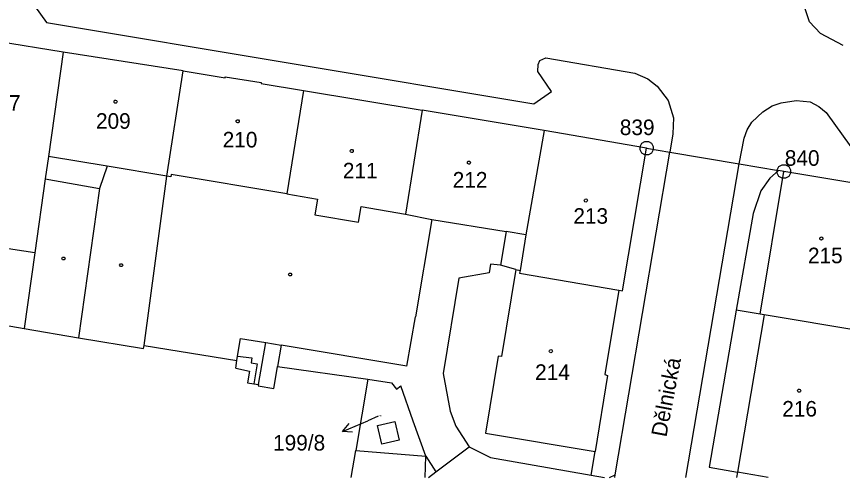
# Model space of a CAD drawing. Extents: x -851495 to -851222, y -1010479 to -1010202.
# Drawn here: x -851400.4 to -851310.2, y -1010478.7 to -1010428.3 of the extents above; entities that cross this region are included whole.
import ezdxf

# ---------------------------------------------------------------- set-up
doc = ezdxf.new("R2010")
doc.units = 0
for name, color, linetype in [('1', 7, 'Continuous'), ('12', 7, 'Continuous'), ('2', 7, 'Continuous'), ('4', 7, 'Continuous'), ('5', 7, 'Continuous'), ('7', 7, 'Continuous'), ('8', 7, 'Continuous')]:
    doc.layers.add(name, color=color, linetype=linetype)

# ---------------------------------------------------------------- blocks, each defined once
blk = doc.blocks.new('101')
blk.add_line((-0.05, 0), (0.05, 0))
blk.add_lwpolyline([(0.19, 0.72), (0.53, 0.53), (0.72, 0.19), (0.72, -0.2), (0.53, -0.54), (0.19, -0.73), (-0.2, -0.73), (-0.54, -0.54), (-0.73, -0.2), (-0.73, 0.19), (-0.54, 0.53), (-0.2, 0.72), (0.19, 0.72)])
blk = doc.blocks.new('10292')
blk.add_line((0, 3), (0, 0))
blk.add_lwpolyline([(-0.5, 2), (0, 3), (0.5, 2)])
blk = doc.blocks.new('402')
blk.add_lwpolyline([(0.09, 0.15), (0.18, 0), (0.09, -0.15), (-0.09, -0.15), (-0.18, 0), (-0.09, 0.15), (0.09, 0.15)])
blk = doc.blocks.new('404')
blk.add_lwpolyline([(0, 0.17), (0.1, 0.15), (0.15, 0.06), (0.17, 0), (0.15, -0.09), (0.07, -0.16), (0, -0.17), (-0.09, -0.14), (-0.15, -0.08), (-0.17, 0), (-0.15, 0.09), (-0.07, 0.16), (0, 0.17)])

msp = doc.modelspace()

# ---------------------------------------------------------------- linework, layer by layer
at = {"layer": '1'}
for p, q in [((-851400.73, -1010423.98), (-851397.15, -1010428.97)), ((-851313.8, -1010428.9), (-851314.31, -1010427.36)), ((-851397.15, -1010428.97), (-851343.91, -1010437.87)), ((-851312.57, -1010430.18), (-851313.8, -1010428.9)), ((-851395.3, -1010432.22), (-851408.97, -1010430.02)), ((-851310.1, -1010431.5), (-851312.57, -1010430.18)), ((-851395.3, -1010432.22), (-851396.92, -1010443.59)), ((-851382.21, -1010434.24), (-851395.3, -1010432.22)), ((-851343.43, -1010433.56), (-851343.23, -1010433.13)), ((-851343.23, -1010433.13), (-851342.57, -1010432.82)), ((-851342.57, -1010432.82), (-851332.86, -1010434.51)), ((-851384, -1010445.76), (-851382.21, -1010434.24)), ((-851382.21, -1010434.24), (-851377.61, -1010435)), ((-851343.47, -1010434.34), (-851343.43, -1010433.56)), ((-851341.96, -1010436.51), (-851343.47, -1010434.34)), ((-851377.61, -1010435), (-851377.6, -1010434.9)), ((-851377.6, -1010434.9), (-851373.69, -1010435.54)), ((-851332.86, -1010434.51), (-851331.45, -1010435.11)), ((-851331.45, -1010435.11), (-851330.43, -1010435.94)), ((-851373.69, -1010435.54), (-851373.7, -1010435.64)), ((-851373.7, -1010435.64), (-851369.07, -1010436.41)), ((-851330.43, -1010435.94), (-851329.24, -1010437.48)), ((-851369.07, -1010436.41), (-851370.87, -1010447.69)), ((-851369.07, -1010436.41), (-851356.11, -1010438.54)), ((-851343.91, -1010437.87), (-851341.96, -1010436.51)), ((-851329.24, -1010437.48), (-851328.64, -1010439.37)), ((-851317.86, -1010438.07), (-851316.87, -1010437.73)), ((-851316.87, -1010437.73), (-851315.23, -1010437.51)), ((-851315.23, -1010437.51), (-851313.7, -1010437.64)), ((-851313.7, -1010437.64), (-851312.78, -1010438.13)), ((-851356.11, -1010438.54), (-851357.92, -1010449.91)), ((-851342.78, -1010440.77), (-851356.11, -1010438.54)), ((-851320.08, -1010439.86), (-851318.88, -1010438.72)), ((-851318.88, -1010438.72), (-851317.86, -1010438.07)), ((-851312.78, -1010438.13), (-851311.97, -1010438.79)), ((-851311.97, -1010438.79), (-851308.42, -1010443.72)), ((-851328.64, -1010439.37), (-851328.72, -1010441.12)), ((-851320.92, -1010441.6), (-851320.6, -1010440.7)), ((-851320.6, -1010440.7), (-851320.08, -1010439.86)), ((-851342.78, -1010440.77), (-851344.77, -1010452.16)), ((-851331.59, -1010442.69), (-851342.78, -1010440.77)), ((-851328.72, -1010441.12), (-851329.05, -1010443.12)), ((-851321.47, -1010444.4), (-851320.92, -1010441.6)), ((-851334.2, -1010458.26), (-851331.59, -1010442.69)), ((-851331.59, -1010442.69), (-851329.05, -1010443.12)), ((-851329.05, -1010443.12), (-851321.47, -1010444.4)), ((-851396.92, -1010443.59), (-851397.27, -1010446.06)), ((-851321.47, -1010444.4), (-851317.17, -1010445.13)), ((-851317.17, -1010445.13), (-851318.12, -1010445.98)), ((-851316.57, -1010445.23), (-851317.17, -1010445.13)), ((-851305.28, -1010447.12), (-851316.57, -1010445.23)), ((-851397.27, -1010446.06), (-851398.42, -1010454.14)), ((-851386.48, -1010464.25), (-851384, -1010445.76)), ((-851383.55, -1010445.83), (-851384, -1010445.76)), ((-851383.51, -1010445.57), (-851383.55, -1010445.83)), ((-851370.87, -1010447.69), (-851383.51, -1010445.57)), ((-851318.12, -1010445.98), (-851319.11, -1010447.34)), ((-851319.11, -1010447.34), (-851319.94, -1010449.84)), ((-851357.92, -1010449.91), (-851355.05, -1010450.5)), ((-851355.05, -1010450.5), (-851346.93, -1010451.78)), ((-851319.94, -1010449.84), (-851321.79, -1010460.39)), ((-851346.93, -1010451.78), (-851347.54, -1010455.48)), ((-851344.77, -1010452.16), (-851346.93, -1010451.78)), ((-851398.42, -1010454.14), (-851404.03, -1010453.26)), ((-851398.42, -1010454.14), (-851399.59, -1010462.37)), ((-851348.62, -1010455.36), (-851348.78, -1010456.31)), ((-851347.54, -1010455.48), (-851348.62, -1010455.36)), ((-851345.85, -1010455.96), (-851347.54, -1010455.48)), ((-851345.85, -1010455.96), (-851345.4, -1010456.04)), ((-851345.4, -1010456.04), (-851345.45, -1010456.36)), ((-851352.09, -1010456.9), (-851353.79, -1010467.29)), ((-851348.78, -1010456.31), (-851352.09, -1010456.9)), ((-851345.45, -1010456.36), (-851334.63, -1010458.19)), ((-851334.63, -1010458.19), (-851336.15, -1010467.42)), ((-851334.63, -1010458.19), (-851334.2, -1010458.26)), ((-851412.88, -1010460.14), (-851399.59, -1010462.37)), ((-851321.79, -1010460.39), (-851324.75, -1010477.53)), ((-851319.17, -1010460.82), (-851321.79, -1010460.39)), ((-851318.74, -1010460.9), (-851319.17, -1010460.82)), ((-851307.9, -1010462.72), (-851318.74, -1010460.9)), ((-851399.59, -1010462.37), (-851393.65, -1010463.42)), ((-851393.65, -1010463.42), (-851386.55, -1010464.56)), ((-851386.55, -1010464.56), (-851386.48, -1010464.25)), ((-851386.48, -1010464.25), (-851376.33, -1010465.88)), ((-851376.46, -1010466.73), (-851376.33, -1010465.88)), ((-851376.46, -1010466.73), (-851374.96, -1010467.04)), ((-851372.16, -1010468.11), (-851371.89, -1010466.54)), ((-851371.89, -1010466.54), (-851362.02, -1010467.9)), ((-851374.96, -1010467.04), (-851375.18, -1010468.3)), ((-851353.79, -1010467.29), (-851353.04, -1010471.42)), ((-851335.85, -1010467.52), (-851337.21, -1010475.8)), ((-851336.15, -1010467.42), (-851335.85, -1010467.52)), ((-851375.18, -1010468.3), (-851374.48, -1010468.42)), ((-851374.48, -1010468.42), (-851373.98, -1010468.51)), ((-851373.98, -1010468.51), (-851374, -1010468.63)), ((-851374, -1010468.63), (-851372.31, -1010468.95)), ((-851372.31, -1010468.95), (-851372.16, -1010468.11)), ((-851362.02, -1010467.9), (-851363.35, -1010475.71)), ((-851362.02, -1010467.9), (-851359.46, -1010468.33)), ((-851359.46, -1010468.33), (-851358.9, -1010469.01)), ((-851358.9, -1010469.01), (-851358.44, -1010468.63)), ((-851357.07, -1010472.5), (-851358.44, -1010468.63)), ((-851353.04, -1010471.42), (-851352.42, -1010473.05)), ((-851355.68, -1010476.31), (-851357.07, -1010472.5)), ((-851352.42, -1010473.05), (-851350.96, -1010475.3)), ((-851363.85, -1010478.65), (-851363.35, -1010475.71)), ((-851363.35, -1010475.71), (-851355.68, -1010476.31)), ((-851354.62, -1010478.05), (-851350.96, -1010475.3)), ((-851350.96, -1010475.3), (-851348.62, -1010476.47)), ((-851337.64, -1010478.4), (-851337.21, -1010475.8)), ((-851355.68, -1010476.31), (-851354.62, -1010478.05)), ((-851348.62, -1010476.47), (-851337.64, -1010478.4)), ((-851324.75, -1010477.53), (-851321.66, -1010478.06)), ((-851337.64, -1010478.4), (-851336.19, -1010478.65)), ((-851335.65, -1010478.65), (-851335.01, -1010478.35)), ((-851335.06, -1010478.65), (-851335.01, -1010478.35)), ((-851321.66, -1010478.06), (-851321.77, -1010478.65)), ((-851318.29, -1010478.65), (-851321.66, -1010478.06))]:
    msp.add_line(p, q, dxfattribs=at)
at = {"layer": '12'}
for p, q in [((-851395.3, -1010432.22), (-851408.97, -1010430.02)), ((-851395.3, -1010432.22), (-851396.92, -1010443.59)), ((-851395.3, -1010432.22), (-851396.92, -1010443.59)), ((-851382.21, -1010434.24), (-851395.3, -1010432.22)), ((-851384, -1010445.76), (-851382.21, -1010434.24)), ((-851384, -1010445.76), (-851382.21, -1010434.24)), ((-851382.21, -1010434.24), (-851377.61, -1010435)), ((-851377.61, -1010435), (-851377.6, -1010434.9)), ((-851377.6, -1010434.9), (-851373.69, -1010435.54)), ((-851373.69, -1010435.54), (-851373.7, -1010435.64)), ((-851373.7, -1010435.64), (-851369.07, -1010436.41)), ((-851369.07, -1010436.41), (-851356.11, -1010438.54)), ((-851342.78, -1010440.77), (-851356.11, -1010438.54)), ((-851342.78, -1010440.77), (-851344.77, -1010452.16)), ((-851342.78, -1010440.77), (-851344.77, -1010452.16)), ((-851331.59, -1010442.69), (-851342.78, -1010440.77)), ((-851334.2, -1010458.26), (-851331.59, -1010442.69)), ((-851396.92, -1010443.59), (-851397.27, -1010446.06)), ((-851390.49, -1010444.67), (-851396.92, -1010443.59)), ((-851384, -1010445.76), (-851390.49, -1010444.67)), ((-851319.17, -1010460.82), (-851316.57, -1010445.23)), ((-851305.28, -1010447.12), (-851316.57, -1010445.23)), ((-851397.27, -1010446.06), (-851398.42, -1010454.14)), ((-851383.55, -1010445.83), (-851384, -1010445.76)), ((-851383.51, -1010445.57), (-851383.55, -1010445.83)), ((-851370.87, -1010447.69), (-851383.51, -1010445.57)), ((-851370.87, -1010447.69), (-851367.54, -1010448.26)), ((-851367.54, -1010448.26), (-851367.83, -1010449.96)), ((-851363.06, -1010450.76), (-851362.77, -1010449.08)), ((-851362.77, -1010449.08), (-851357.92, -1010449.91)), ((-851367.83, -1010449.96), (-851363.06, -1010450.76)), ((-851357.92, -1010449.91), (-851355.05, -1010450.5)), ((-851355.05, -1010450.5), (-851346.93, -1010451.78)), ((-851344.77, -1010452.16), (-851346.93, -1010451.78)), ((-851344.77, -1010452.16), (-851345.4, -1010456.04)), ((-851398.42, -1010454.14), (-851404.03, -1010453.26)), ((-851345.85, -1010455.96), (-851347.44, -1010465.45)), ((-851345.85, -1010455.96), (-851345.4, -1010456.04)), ((-851345.4, -1010456.04), (-851345.45, -1010456.36)), ((-851345.4, -1010456.04), (-851345.45, -1010456.36)), ((-851345.45, -1010456.36), (-851334.63, -1010458.19)), ((-851345.45, -1010456.36), (-851334.63, -1010458.19)), ((-851334.63, -1010458.19), (-851336.15, -1010467.42)), ((-851334.63, -1010458.19), (-851334.2, -1010458.26)), ((-851318.74, -1010460.9), (-851321.66, -1010478.06)), ((-851318.74, -1010460.9), (-851319.17, -1010460.82)), ((-851347.81, -1010465.39), (-851349.18, -1010473.8)), ((-851347.44, -1010465.45), (-851347.81, -1010465.39)), ((-851335.85, -1010467.52), (-851337.21, -1010475.8)), ((-851336.15, -1010467.42), (-851335.85, -1010467.52)), ((-851349.18, -1010473.8), (-851337.21, -1010475.8)), ((-851321.66, -1010478.06), (-851321.77, -1010478.65)), ((-851318.29, -1010478.65), (-851321.66, -1010478.06)), ((-851318.29, -1010478.65), (-851321.66, -1010478.06))]:
    msp.add_line(p, q, dxfattribs=at)
at = {"layer": '4'}
for p, q in [((-851335.01, -1010478.35), (-851329.05, -1010443.12)), ((-851390.49, -1010444.67), (-851396.92, -1010443.59)), ((-851390.49, -1010444.67), (-851391.35, -1010447.1)), ((-851384, -1010445.76), (-851390.49, -1010444.67)), ((-851327.29, -1010478.65), (-851321.47, -1010444.4)), ((-851319.17, -1010460.82), (-851316.57, -1010445.23)), ((-851397.27, -1010446.06), (-851391.35, -1010447.1)), ((-851391.35, -1010447.1), (-851393.65, -1010463.42)), ((-851370.87, -1010447.69), (-851367.54, -1010448.26)), ((-851367.54, -1010448.26), (-851367.83, -1010449.96)), ((-851363.06, -1010450.76), (-851362.77, -1010449.08)), ((-851362.77, -1010449.08), (-851357.92, -1010449.91)), ((-851367.83, -1010449.96), (-851363.06, -1010450.76)), ((-851355.05, -1010450.5), (-851356.84, -1010461.11)), ((-851344.77, -1010452.16), (-851345.4, -1010456.04)), ((-851345.85, -1010455.96), (-851347.44, -1010465.45)), ((-851357.76, -1010466.48), (-851356.84, -1010461.11)), ((-851318.74, -1010460.9), (-851321.66, -1010478.06)), ((-851376.26, -1010465.39), (-851375.94, -1010463.46)), ((-851375.94, -1010463.46), (-851373.19, -1010463.93)), ((-851373.98, -1010468.51), (-851373.19, -1010463.93)), ((-851373.19, -1010463.93), (-851371.49, -1010464.21)), ((-851371.49, -1010464.21), (-851371.89, -1010466.54)), ((-851357.76, -1010466.48), (-851371.49, -1010464.21)), ((-851376.33, -1010465.88), (-851376.26, -1010465.39)), ((-851376.26, -1010465.39), (-851374.69, -1010465.58)), ((-851374.69, -1010465.58), (-851374.78, -1010466.13)), ((-851347.81, -1010465.39), (-851349.18, -1010473.8)), ((-851347.44, -1010465.45), (-851347.81, -1010465.39)), ((-851374.78, -1010466.13), (-851374.11, -1010466.25)), ((-851374.11, -1010466.25), (-851374.48, -1010468.42)), ((-851360.97, -1010472.97), (-851359.08, -1010472.55)), ((-851360.51, -1010475), (-851360.97, -1010472.97)), ((-851359.08, -1010472.55), (-851358.62, -1010474.59)), ((-851349.18, -1010473.8), (-851337.21, -1010475.8)), ((-851358.62, -1010474.59), (-851360.51, -1010475)), ((-851355.77, -1010478.65), (-851355.68, -1010476.31)), ((-851355.42, -1010478.65), (-851354.62, -1010478.05))]:
    msp.add_line(p, q, dxfattribs=at)
at = {"layer": '7'}
msp.add_line((-851360.92, -1010471.97), (-851362.05, -1010472.45), dxfattribs=at)

# ---------------------------------------------------------------- block references
at = {"layer": '5'}
for name, p in [('404', (-851389.59, -1010437.63)), ('404', (-851376.25, -1010439.76)), ('404', (-851363.79, -1010443.01)), ('404', (-851350.99, -1010444.28)), ('404', (-851338.22, -1010448.41)), ('404', (-851312.49, -1010452.56)), ('402', (-851395.29, -1010454.75)), ('402', (-851388.97, -1010455.47)), ('402', (-851370.53, -1010456.5)), ('404', (-851342.04, -1010464.86)), ('404', (-851314.91, -1010469.18))]:
    msp.add_blockref(name, p, dxfattribs=at)
at = {"layer": '7', "rotation": 113.101869}
msp.add_blockref('10292', (-851362.05, -1010472.45), dxfattribs=at)
at = {"layer": '8'}
for p in [(-851331.57, -1010442.69), (-851316.58, -1010445.24)]:
    msp.add_blockref('101', p, dxfattribs=at)

# ---------------------------------------------------------------- texts
at = {"layer": '2'}
for s, height, p in [('207', 1.7, (-851403.76, -1010438.61)), ('209', 1.7, (-851391.73, -1010440.58)), ('210', 1.7, (-851377.89, -1010442.62)), ('211', 1.7, (-851364.76, -1010446)), ('212', 1.7, (-851352.76, -1010447)), ('213', 1.7, (-851339.58, -1010450.95)), ('215', 1.7, (-851313.95, -1010455.26)), ('214', 1.7, (-851343.76, -1010468)), ('216', 1.7, (-851316.76, -1010472)), ('199/8', 0.1, (-851360.9, -1010471.97))]:
    msp.add_text(s, height=height, dxfattribs=at).set_placement(p)
at = {"layer": '7'}
msp.add_text('Dělnická', height=1.7, rotation=79.412, dxfattribs=at).set_placement((-851329.42, -1010474.31))
msp.add_text('199/8', height=1.7, dxfattribs=at).set_placement((-851372.384, -1010475.71))
at = {"layer": '8'}
for s, p in [('839', (-851334.503, -1010441.27)), ('840', (-851316.48, -1010444.62))]:
    msp.add_text(s, height=1.7, dxfattribs=at).set_placement(p)

doc.saveas('drawing.dxf')
